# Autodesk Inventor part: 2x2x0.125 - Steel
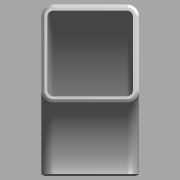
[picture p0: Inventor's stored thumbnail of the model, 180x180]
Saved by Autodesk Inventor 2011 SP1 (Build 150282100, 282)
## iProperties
Created: 2011-03
Part Number: 2x2x0.125 - Steel
Material: Default
Document SubType Name: Modeling
Designer: bamfomg
Density: 1 g/cm^3
Author: bamfomg
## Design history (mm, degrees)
derived "Square Tube Corners.ipt" dims "d2" = 25.4, "d3" = 25.4, "d6" = 3.175, "d7" = 3.175, "d8" = 3.175, "d12" = 90 deg, "d16" = 1.5875, "d18" = 30 deg, "ID_Rad" = 3.175, "OD_Rad" = 6.35, "Side_One" = 50.8, "Side_Two" = 50.8, "Thickness" = 3.175, "Bend_IDRad" = 38.1, "Bevel_Angl" = 30 deg, "Bevel_Dist" = 1.5875
body "Solid1"
feature "Solid1::Square Tube Corners.ipt" dims "d2" = 25.4, "d3" = 25.4, "d6" = 3.175, "d7" = 3.175, "d8" = 3.175, "d12" = 90 deg, "d16" = 1.5875, "d18" = 30 deg, "ID_Rad" = 3.175, "OD_Rad" = 6.35, "Side_One" = 50.8, "Side_Two" = 50.8, "Thickness" = 3.175, "Bend_IDRad" = 38.1, "Bevel_Angl" = 30 deg, "Bevel_Dist" = 1.5875, "ScaleForDerivedMember" = 10
tag "TaggingFeature1"
